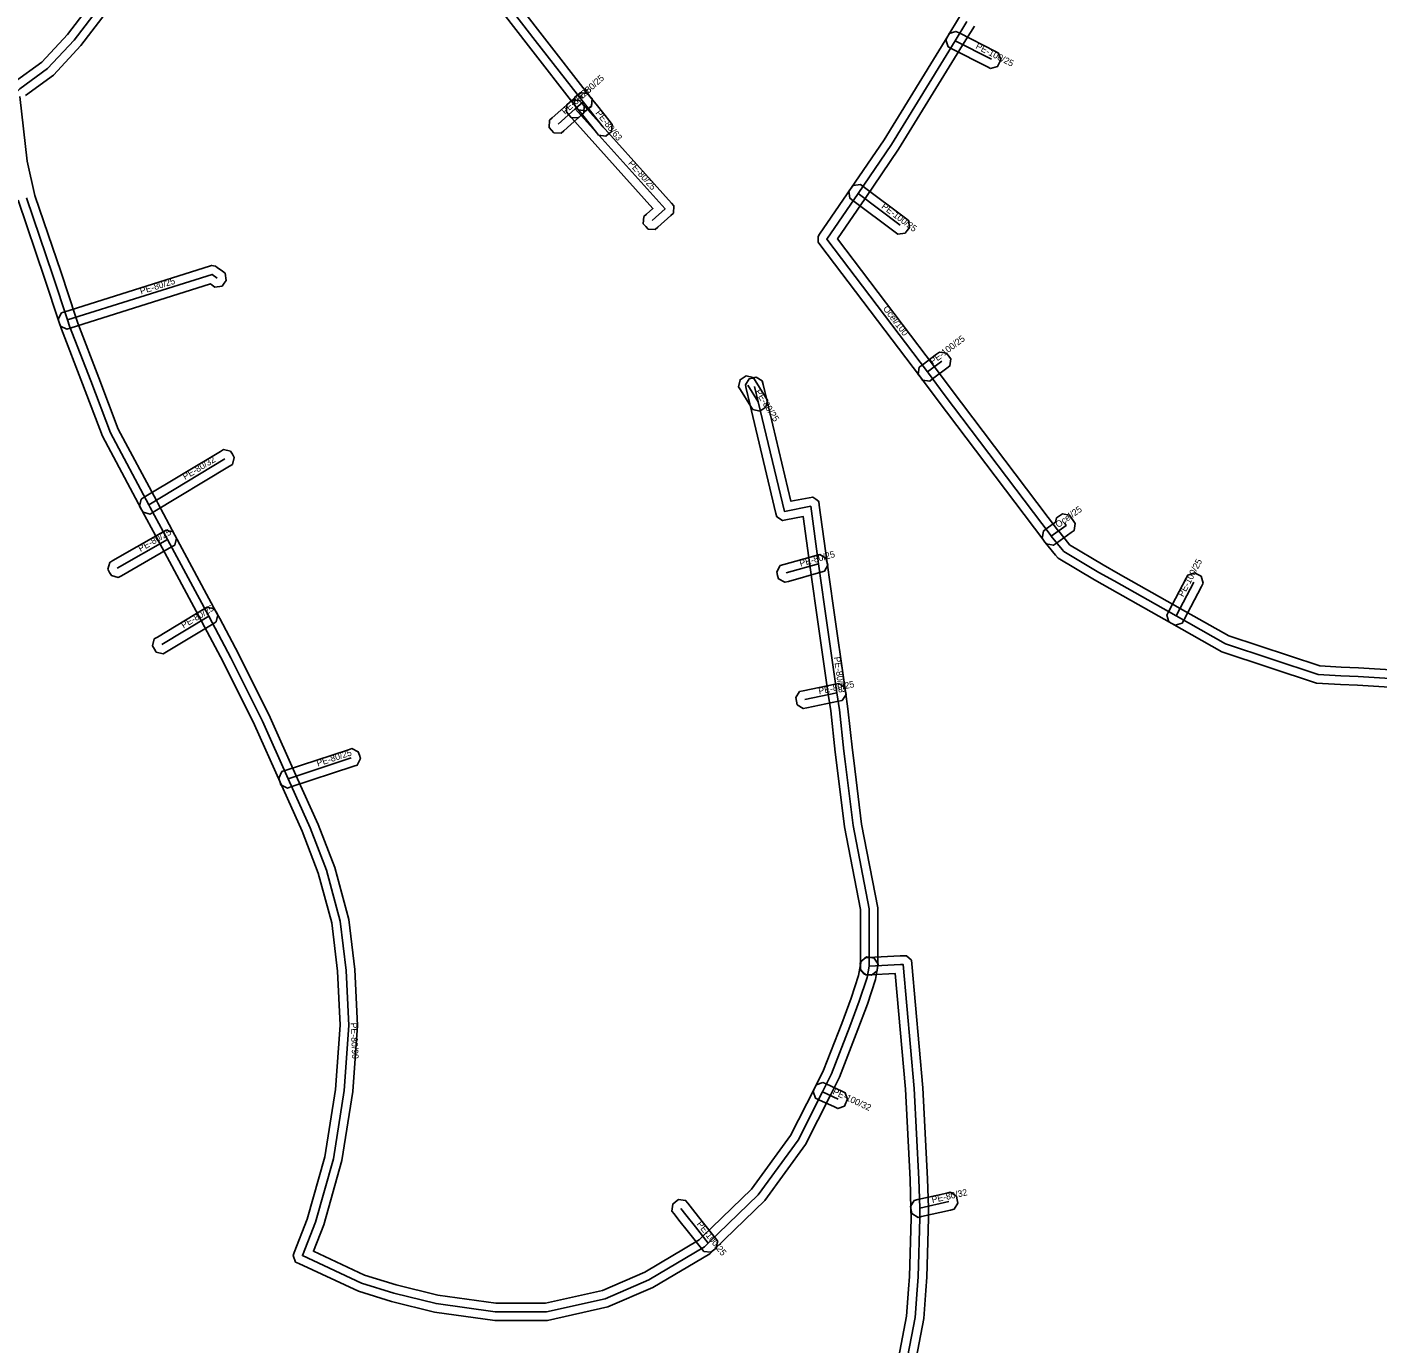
# Model space of a CAD drawing. Extents: x -569373 to -565022, y -1135090 to -1131496.
# Drawn here: x -565687.7 to -565532.3, y -1133998.2 to -1133846.6 of the extents above; entities that cross this region are included whole.
import ezdxf

# ---------------------------------------------------------------- set-up
doc = ezdxf.new("R2010")
doc.units = 0
for name, color, linetype in [('1', 7, 'Continuous'), ('24', 7, 'Continuous'), ('30', 7, 'Continuous')]:
    doc.layers.add(name, color=color, linetype=linetype)

msp = doc.modelspace()

# ---------------------------------------------------------------- linework, layer by layer
at = {"layer": '1'}
for points in [[(-565640.381, -1133832.1), (-565628.421, -1133847.596), (-565622.903, -1133854.633), (-565622.647, -1133854.959), (-565622.747, -1133855.781), (-565623.073, -1133856.037), (-565623.399, -1133856.293), (-565624.221, -1133856.193), (-565624.477, -1133855.867), (-565629.999, -1133848.824), (-565641.919, -1133833.38)], [(-565689.224, -1133853.006), (-565686.016, -1133850.687), (-565683.056, -1133847.495), (-565673.112, -1133834.485)], [(-565671.524, -1133835.699), (-565681.524, -1133848.785), (-565684.684, -1133852.193), (-565687.896, -1133854.514)], [(-565525.264, -1133923.028), (-565534.506, -1133922.438), (-565536.498, -1133922.344), (-565539.245, -1133922.212), (-565550.147, -1133918.589), (-565555.911, -1133915.341), (-565563.054, -1133911.303), (-565564.802, -1133910.315), (-565568.991, -1133907.816), (-565569.299, -1133907.46), (-565570.627, -1133905.802), (-565570.642, -1133905.771), (-565582.93, -1133889.551), (-565584.744, -1133887.114), (-565584.852, -1133886.967), (-565596.427, -1133871.673), (-565596.621, -1133871.416), (-565596.637, -1133870.772), (-565596.456, -1133870.506), (-565592.866, -1133865.246), (-565589.04, -1133859.636), (-565581.702, -1133847.696), (-565580.34, -1133845.483)], [(-565578.64, -1133846.537), (-565579.998, -1133848.744), (-565587.36, -1133860.724), (-565591.214, -1133866.374), (-565594.399, -1133871.04), (-565583.248, -1133885.773), (-565583.136, -1133885.926), (-565581.33, -1133888.349), (-565568.937, -1133904.71), (-565568.932, -1133904.719), (-565567.761, -1133906.18), (-565567.689, -1133906.264), (-565563.798, -1133908.585), (-565562.07, -1133909.563), (-565554.929, -1133913.599), (-565549.333, -1133916.751), (-565538.875, -1133920.228), (-565536.402, -1133920.346), (-565534.394, -1133920.442), (-565525.136, -1133921.032)], [(-565688.56, -1133854.659), (-565687.713, -1133862.093), (-565686.826, -1133866.029), (-565683.802, -1133874.933), (-565682.109, -1133880.069), (-565681.887, -1133880.755), (-565679.456, -1133887.032), (-565677.217, -1133892.946), (-565672.827, -1133901.19), (-565672.668, -1133901.488), (-565670.689, -1133905.177), (-565665.93, -1133914.035), (-565665.539, -1133914.756), (-565663.361, -1133918.832), (-565659.725, -1133926.154), (-565656.757, -1133932.802), (-565654.207, -1133938.495), (-565652.289, -1133943.448), (-565650.666, -1133949.438), (-565649.963, -1133955.196), (-565649.668, -1133961.634), (-565650.226, -1133969.244), (-565651.471, -1133977.184), (-565653.561, -1133984.589), (-565654.747, -1133987.62), (-565648.848, -1133990.366), (-565645.211, -1133991.506), (-565640.432, -1133992.677), (-565633.742, -1133993.61), (-565628.012, -1133993.59), (-565621.479, -1133992.134), (-565616.585, -1133990.027), (-565610.313, -1133986.305), (-565609.969, -1133985.985), (-565604.288, -1133980.482), (-565599.796, -1133974.297), (-565597.022, -1133968.819), (-565595.995, -1133966.784), (-565593.915, -1133961.386), (-565592.844, -1133958.499), (-565591.972, -1133955.856), (-565591.755, -1133954.617), (-565591.683, -1133954.209), (-565591.005, -1133953.733), (-565590.597, -1133953.805), (-565590.189, -1133953.877), (-565589.713, -1133954.555), (-565589.785, -1133954.963), (-565590.028, -1133956.344), (-565590.956, -1133959.161), (-565592.045, -1133962.094), (-565594.165, -1133967.596), (-565595.238, -1133969.721), (-565598.084, -1133975.343), (-565602.772, -1133981.798), (-565608.591, -1133987.435), (-565609.107, -1133987.915), (-565615.675, -1133991.813), (-565620.861, -1133994.046), (-565627.788, -1133995.59), (-565633.878, -1133995.61), (-565640.808, -1133994.643), (-565645.749, -1133993.434), (-565649.572, -1133992.234), (-565656.442, -1133989.037), (-565656.801, -1133988.87), (-565657.095, -1133988.134), (-565656.951, -1133987.766), (-565655.459, -1133983.951), (-565653.429, -1133976.756), (-565652.214, -1133969.016), (-565651.672, -1133961.606), (-565651.957, -1133955.364), (-565652.634, -1133949.822), (-565654.191, -1133944.072), (-565656.053, -1133939.265), (-565658.583, -1133933.618), (-565661.535, -1133927.006), (-565665.139, -1133919.748), (-565667.301, -1133915.704), (-565667.69, -1133914.985), (-565672.451, -1133906.123), (-565674.432, -1133902.432), (-565674.593, -1133902.13), (-565679.043, -1133893.774), (-565681.324, -1133887.748), (-565683.773, -1133881.425), (-565684.011, -1133880.691), (-565685.698, -1133875.567), (-565688.754, -1133866.571)], [(-565588.581, -1134006.194), (-565586.453, -1133995.11), (-565586.234, -1133992.009), (-565586.129, -1133990.528), (-565585.91, -1133983.827), (-565585.94, -1133982.688), (-565586.039, -1133979.371), (-565586.578, -1133968.96), (-565587.752, -1133955.65), (-565590.723, -1133955.789), (-565591.137, -1133955.808), (-565591.75, -1133955.251), (-565591.769, -1133954.837), (-565591.788, -1133954.423), (-565591.231, -1133953.81), (-565590.817, -1133953.791), (-565587.18, -1133953.621), (-565586.873, -1133953.611), (-565586.475, -1133953.598), (-565585.879, -1133954.125), (-565585.844, -1133954.522), (-565584.582, -1133968.82), (-565584.041, -1133979.289), (-565583.94, -1133982.632), (-565583.91, -1133983.833), (-565584.131, -1133990.632), (-565584.238, -1133992.151), (-565584.467, -1133995.37), (-565586.619, -1134006.586)]]:
    msp.add_lwpolyline(points, dxfattribs=at)
for points in [[(-565576.766, -1133851.429), (-565577.135, -1133851.241), (-565581.305, -1133849.111), (-565581.674, -1133848.923), (-565581.929, -1133848.134), (-565581.741, -1133847.765), (-565581.553, -1133847.396), (-565580.764, -1133847.141), (-565580.395, -1133847.329), (-565576.225, -1133849.459), (-565575.856, -1133849.647), (-565575.601, -1133850.436), (-565575.789, -1133850.805), (-565575.977, -1133851.174)], [(-565627.557, -1133857.383), (-565627.249, -1133857.106), (-565625.269, -1133855.326), (-565624.961, -1133855.049), (-565624.133, -1133855.093), (-565623.856, -1133855.401), (-565623.579, -1133855.709), (-565623.623, -1133856.537), (-565623.931, -1133856.814), (-565625.911, -1133858.594), (-565626.219, -1133858.871), (-565627.047, -1133858.827), (-565627.324, -1133858.519), (-565627.601, -1133858.211)], [(-565624.133, -1133855.094), (-565623.856, -1133855.402), (-565613.506, -1133866.932), (-565613.229, -1133867.24), (-565613.273, -1133868.067), (-565613.581, -1133868.344), (-565615.071, -1133869.684), (-565615.379, -1133869.961), (-565616.207, -1133869.917), (-565616.484, -1133869.609), (-565616.761, -1133869.301), (-565616.717, -1133868.473), (-565616.409, -1133868.196), (-565615.662, -1133867.525), (-565625.344, -1133856.738), (-565625.621, -1133856.43), (-565625.576, -1133855.603), (-565625.268, -1133855.326), (-565624.96, -1133855.049)], [(-565625.577, -1133855.605), (-565625.269, -1133855.327), (-565624.359, -1133854.507), (-565624.052, -1133854.23), (-565623.225, -1133854.273), (-565622.947, -1133854.581), (-565622.67, -1133854.888), (-565622.713, -1133855.715), (-565623.021, -1133855.993), (-565623.931, -1133856.813), (-565624.238, -1133857.09), (-565625.065, -1133857.047), (-565625.343, -1133856.739), (-565625.62, -1133856.432)], [(-565623.16, -1133854.306), (-565622.904, -1133854.632), (-565622.055, -1133855.71), (-565620.597, -1133857.548), (-565620.339, -1133857.873), (-565620.434, -1133858.696), (-565620.758, -1133858.953), (-565621.083, -1133859.211), (-565621.906, -1133859.116), (-565622.163, -1133858.792), (-565623.625, -1133856.95), (-565624.476, -1133855.868), (-565624.732, -1133855.543), (-565624.634, -1133854.72), (-565624.308, -1133854.464), (-565623.983, -1133854.208)], [(-565591.771, -1133864.761), (-565591.44, -1133865.01), (-565586.57, -1133868.66), (-565586.239, -1133868.909), (-565586.121, -1133869.729), (-565586.37, -1133870.06), (-565586.619, -1133870.391), (-565587.439, -1133870.509), (-565587.77, -1133870.26), (-565592.64, -1133866.61), (-565592.971, -1133866.361), (-565593.089, -1133865.541), (-565592.84, -1133865.21), (-565592.591, -1133864.879)], [(-565683.756, -1133879.551), (-565683.361, -1133879.426), (-565666.711, -1133874.176), (-565666.482, -1133874.104), (-565666.007, -1133874.184), (-565665.814, -1133874.327), (-565665.234, -1133874.757), (-565664.901, -1133875.003), (-565664.78, -1133875.823), (-565665.027, -1133876.156), (-565665.273, -1133876.489), (-565666.093, -1133876.61), (-565666.426, -1133876.363), (-565666.596, -1133876.237), (-565682.759, -1133881.334), (-565683.154, -1133881.458), (-565683.889, -1133881.076), (-565684.014, -1133880.681), (-565684.138, -1133880.286)], [(-565584.984, -1133885.823), (-565584.654, -1133885.573), (-565583.004, -1133884.323), (-565582.674, -1133884.073), (-565581.853, -1133884.186), (-565581.603, -1133884.516), (-565581.353, -1133884.846), (-565581.466, -1133885.667), (-565581.796, -1133885.917), (-565583.446, -1133887.167), (-565583.776, -1133887.417), (-565584.597, -1133887.304), (-565584.847, -1133886.974), (-565585.097, -1133886.644)], [(-565604.144, -1133890.694), (-565604.365, -1133890.344), (-565605.585, -1133888.414), (-565605.807, -1133888.064), (-565605.624, -1133887.256), (-565605.274, -1133887.035), (-565604.924, -1133886.813), (-565604.116, -1133886.996), (-565603.895, -1133887.346), (-565602.675, -1133889.276), (-565602.453, -1133889.626), (-565602.636, -1133890.434), (-565602.986, -1133890.655), (-565603.336, -1133890.877)], [(-565591.818, -1133955.059), (-565591.76, -1133954.649), (-565591.74, -1133954.509), (-565591.74, -1133948.277), (-565593.598, -1133938.748), (-565594.523, -1133931.336), (-565594.654, -1133930.14), (-565595.182, -1133925.396), (-565595.46, -1133923.462), (-565596.89, -1133913.53), (-565597.571, -1133908.606), (-565598.337, -1133903.02), (-565600.332, -1133903.402), (-565600.726, -1133903.478), (-565601.4, -1133903.042), (-565601.493, -1133902.651), (-565604.493, -1133890.041), (-565604.913, -1133888.271), (-565605.009, -1133887.868), (-565604.574, -1133887.163), (-565604.171, -1133887.067), (-565603.768, -1133886.971), (-565603.063, -1133887.406), (-565602.967, -1133887.809), (-565602.547, -1133889.579), (-565599.769, -1133901.258), (-565597.678, -1133900.858), (-565597.256, -1133900.777), (-565596.907, -1133901.028), (-565596.558, -1133901.278), (-565596.499, -1133901.704), (-565595.589, -1133908.334), (-565594.91, -1133913.25), (-565593.48, -1133923.178), (-565593.198, -1133925.144), (-565592.666, -1133929.92), (-565592.537, -1133931.104), (-565591.622, -1133938.432), (-565589.74, -1133948.083), (-565589.74, -1133954.651), (-565589.78, -1133954.931), (-565589.838, -1133955.341), (-565590.501, -1133955.838), (-565590.911, -1133955.78), (-565591.321, -1133955.722)], [(-565674.582, -1133901.018), (-565674.227, -1133900.804), (-565665.457, -1133895.514), (-565665.102, -1133895.3), (-565664.298, -1133895.498), (-565664.084, -1133895.853), (-565663.87, -1133896.208), (-565664.068, -1133897.012), (-565664.423, -1133897.226), (-565673.193, -1133902.516), (-565673.548, -1133902.73), (-565674.352, -1133902.532), (-565674.566, -1133902.177), (-565674.78, -1133901.822)], [(-565570.36, -1133904.445), (-565569.281, -1133903.677), (-565569.189, -1133903.172), (-565568.848, -1133902.937), (-565568.507, -1133902.702), (-565567.692, -1133902.851), (-565567.457, -1133903.192), (-565567.257, -1133903.482), (-565567.024, -1133903.819), (-565567.166, -1133904.627), (-565567.5, -1133904.865), (-565569.2, -1133906.075), (-565569.538, -1133906.315), (-565570.355, -1133906.178), (-565570.595, -1133905.84), (-565570.835, -1133905.502), (-565570.698, -1133904.685)], [(-565670.713, -1133906.312), (-565671.073, -1133906.518), (-565676.853, -1133909.828), (-565677.213, -1133910.034), (-565678.012, -1133909.817), (-565678.218, -1133909.457), (-565678.424, -1133909.097), (-565678.207, -1133908.298), (-565677.847, -1133908.092), (-565672.067, -1133904.782), (-565671.707, -1133904.576), (-565670.908, -1133904.793), (-565670.702, -1133905.153), (-565670.496, -1133905.513)], [(-565600.999, -1133908.669), (-565600.6, -1133908.557), (-565596.85, -1133907.507), (-565596.451, -1133907.395), (-565595.729, -1133907.801), (-565595.617, -1133908.2), (-565595.505, -1133908.599), (-565595.911, -1133909.321), (-565596.31, -1133909.433), (-565600.06, -1133910.483), (-565600.459, -1133910.595), (-565601.181, -1133910.189), (-565601.293, -1133909.79), (-565601.405, -1133909.391)], [(-565552.293, -1133910.691), (-565552.486, -1133911.057), (-565554.536, -1133914.937), (-565554.729, -1133915.303), (-565555.521, -1133915.547), (-565555.887, -1133915.354), (-565556.253, -1133915.161), (-565556.497, -1133914.369), (-565556.304, -1133914.003), (-565554.254, -1133910.123), (-565554.061, -1133909.757), (-565553.269, -1133909.513), (-565552.903, -1133909.706), (-565552.537, -1133909.899)], [(-565665.939, -1133915.152), (-565666.294, -1133915.366), (-565671.684, -1133918.616), (-565672.039, -1133918.83), (-565672.842, -1133918.631), (-565673.056, -1133918.276), (-565673.27, -1133917.921), (-565673.071, -1133917.118), (-565672.716, -1133916.904), (-565667.326, -1133913.654), (-565666.971, -1133913.44), (-565666.168, -1133913.639), (-565665.954, -1133913.994), (-565665.74, -1133914.349)], [(-565593.862, -1133924.215), (-565594.268, -1133924.299), (-565597.948, -1133925.059), (-565598.354, -1133925.143), (-565599.045, -1133924.688), (-565599.129, -1133924.282), (-565599.213, -1133923.876), (-565598.758, -1133923.185), (-565598.352, -1133923.101), (-565594.672, -1133922.341), (-565594.266, -1133922.257), (-565593.575, -1133922.712), (-565593.491, -1133923.118), (-565593.407, -1133923.524)], [(-565658.377, -1133932.39), (-565657.983, -1133932.26), (-565650.723, -1133929.87), (-565650.329, -1133929.74), (-565649.59, -1133930.113), (-565649.46, -1133930.507), (-565649.33, -1133930.901), (-565649.703, -1133931.64), (-565650.097, -1133931.77), (-565657.357, -1133934.16), (-565657.751, -1133934.29), (-565658.49, -1133933.917), (-565658.62, -1133933.523), (-565658.75, -1133933.129)], [(-565596.082, -1133968.189), (-565595.707, -1133968.364), (-565593.907, -1133969.204), (-565593.532, -1133969.379), (-565593.249, -1133970.158), (-565593.424, -1133970.533), (-565593.599, -1133970.908), (-565594.378, -1133971.191), (-565594.753, -1133971.016), (-565596.553, -1133970.176), (-565596.928, -1133970.001), (-565597.211, -1133969.222), (-565597.036, -1133968.847), (-565596.861, -1133968.472)], [(-565585.563, -1133981.775), (-565585.159, -1133981.684), (-565581.819, -1133980.934), (-565581.415, -1133980.843), (-565580.715, -1133981.287), (-565580.624, -1133981.691), (-565580.533, -1133982.095), (-565580.977, -1133982.795), (-565581.381, -1133982.886), (-565584.721, -1133983.636), (-565585.125, -1133983.727), (-565585.825, -1133983.283), (-565585.916, -1133982.879), (-565586.007, -1133982.475)], [(-565609.81, -1133987.654), (-565610.066, -1133987.329), (-565611.544, -1133985.45), (-565612.665, -1133984.04), (-565613.216, -1133983.338), (-565613.472, -1133983.012), (-565613.374, -1133982.19), (-565613.048, -1133981.934), (-565612.722, -1133981.678), (-565611.9, -1133981.776), (-565611.644, -1133982.102), (-565611.095, -1133982.8), (-565609.976, -1133984.21), (-565608.494, -1133986.091), (-565608.238, -1133986.417), (-565608.336, -1133987.24), (-565608.661, -1133987.496), (-565608.987, -1133987.752)]]:
    msp.add_lwpolyline(points, close=True, dxfattribs=at)
at = {"layer": '24'}
for points in [[(-565689.7, -1133854.98), (-565688.56, -1133853.76), (-565685.35, -1133851.44), (-565682.29, -1133848.14), (-565672.318, -1133835.092), (-565671.59, -1133834.14), (-565658.14, -1133816.52), (-565652.84, -1133820.6), (-565648.38, -1133824.67), (-565641.15, -1133832.74), (-565629.21, -1133848.21), (-565623.69, -1133855.25)], [(-565579.49, -1133846.01), (-565580.85, -1133848.22), (-565588.2, -1133860.18), (-565592.04, -1133865.81), (-565595.63, -1133871.07), (-565584.05, -1133886.37), (-565583.94, -1133886.52), (-565582.13, -1133888.95), (-565569.79, -1133905.24), (-565569.78, -1133905.26), (-565568.53, -1133906.82), (-565568.34, -1133907.04), (-565564.3, -1133909.45), (-565562.562, -1133910.433), (-565555.42, -1133914.47), (-565549.74, -1133917.67), (-565539.06, -1133921.22), (-565536.45, -1133921.345), (-565534.45, -1133921.44), (-565525.2, -1133922.03), (-565516.66, -1133922.58), (-565513.93, -1133922.75), (-565511.94, -1133922.9), (-565507.76, -1133923.22)], [(-565576.68, -1133850.35), (-565580.85, -1133848.22)], [(-565624.6, -1133856.07), (-565623.69, -1133855.25)], [(-565623.69, -1133855.25), (-565622.84, -1133856.33), (-565621.38, -1133858.17)], [(-565626.58, -1133857.85), (-565624.6, -1133856.07)], [(-565624.6, -1133856.07), (-565614.25, -1133867.6), (-565615.74, -1133868.94)], [(-565687.79, -1133866.3), (-565684.75, -1133875.25), (-565683.06, -1133880.38), (-565682.83, -1133881.09), (-565680.39, -1133887.39), (-565678.13, -1133893.36), (-565673.71, -1133901.66), (-565673.55, -1133901.96), (-565671.57, -1133905.65), (-565666.81, -1133914.51), (-565666.42, -1133915.23), (-565664.25, -1133919.29), (-565660.63, -1133926.58), (-565657.67, -1133933.21), (-565655.13, -1133938.88), (-565653.24, -1133943.76), (-565651.65, -1133949.63), (-565650.96, -1133955.28), (-565650.67, -1133961.62), (-565651.22, -1133969.13), (-565652.45, -1133976.97), (-565654.51, -1133984.27), (-565656.02, -1133988.13), (-565649.21, -1133991.3), (-565645.48, -1133992.47), (-565640.62, -1133993.66), (-565633.81, -1133994.61), (-565627.9, -1133994.59), (-565621.17, -1133993.09), (-565616.13, -1133990.92), (-565609.71, -1133987.11), (-565609.28, -1133986.71), (-565603.53, -1133981.14), (-565598.94, -1133974.82), (-565596.13, -1133969.27), (-565595.08, -1133967.19), (-565592.98, -1133961.74), (-565591.9, -1133958.83), (-565591, -1133956.1), (-565590.77, -1133954.79)], [(-565592.04, -1133865.81), (-565587.17, -1133869.46)], [(-565683.06, -1133880.38), (-565666.41, -1133875.13), (-565665.83, -1133875.56)], [(-565584.05, -1133886.37), (-565582.4, -1133885.12)], [(-565603.52, -1133889.81), (-565604.74, -1133887.88)], [(-565590.77, -1133954.79), (-565590.74, -1133954.58), (-565590.74, -1133948.18), (-565592.61, -1133938.59), (-565593.53, -1133931.22), (-565593.66, -1133930.03), (-565594.19, -1133925.27), (-565594.47, -1133923.32), (-565595.9, -1133913.39), (-565596.58, -1133908.47), (-565597.49, -1133901.84), (-565600.52, -1133902.42), (-565603.52, -1133889.81), (-565603.94, -1133888.04)], [(-565673.71, -1133901.66), (-565664.94, -1133896.37)], [(-565569.78, -1133905.26), (-565568.08, -1133904.05), (-565568.28, -1133903.76)], [(-565671.57, -1133905.65), (-565677.35, -1133908.96)], [(-565600.33, -1133909.52), (-565596.58, -1133908.47)], [(-565553.37, -1133910.59), (-565555.42, -1133914.47)], [(-565666.81, -1133914.51), (-565672.2, -1133917.76)], [(-565594.47, -1133923.32), (-565598.15, -1133924.08)], [(-565657.67, -1133933.21), (-565650.41, -1133930.82)], [(-565590.77, -1133954.79), (-565587.14, -1133954.62), (-565586.84, -1133954.61), (-565585.58, -1133968.89), (-565585.04, -1133979.33), (-565584.94, -1133982.66), (-565584.91, -1133983.83), (-565585.13, -1133990.58), (-565585.236, -1133992.08), (-565585.46, -1133995.24), (-565587.6, -1134006.39)], [(-565596.13, -1133969.27), (-565594.33, -1133970.11)], [(-565609.28, -1133986.71), (-565610.76, -1133984.83), (-565611.88, -1133983.42), (-565612.43, -1133982.72)], [(-565584.94, -1133982.66), (-565581.6, -1133981.91)]]:
    msp.add_lwpolyline(points, dxfattribs=at)

# ---------------------------------------------------------------- texts
at = {"layer": '30'}
for s, rotation, p in [('PE-100/25', 332.94245, (-565578.565, -1133849.085)), ('PE-80/25', 42.02198, (-565624.308, -1133855.427)), ('PE-80/25', 41.95522, (-565625.79, -1133856.76)), ('PE-80/63', 308.43124, (-565622.306, -1133856.551)), ('PE-80/25', 311.913, (-565618.556, -1133862.381)), ('PE-100/25', 323.14893, (-565589.405, -1133867.435)), ('PE-80/25', 17.50086, (-565674.591, -1133877.446)), ('Ocel/100', 307.12072, (-565589.206, -1133879.093)), ('PE-100/25', 37.14669, (-565583.425, -1133885.545)), ('PE-80/25', 302.29798, (-565603.93, -1133888.645)), ('PE-80/32', 31.09807, (-565669.525, -1133898.815)), ('Ocel/25', 35.44192, (-565568.986, -1133904.353)), ('PE-80/25', 29.79823, (-565674.66, -1133907.105)), ('PE-80/25', 15.64225, (-565598.655, -1133908.795)), ('PE-100/25', 62.15024, (-565554.595, -1133912.33)), ('PE-80/25', 31.08865, (-565669.705, -1133915.935)), ('PE-80/63', 278.19472, (-565594.832, -1133919.215)), ('PE-80/25', 11.66877, (-565596.51, -1133923.5)), ('PE-80/25', 18.2216, (-565654.24, -1133931.815)), ('PE-80/90', 272.61896, (-565650.475, -1133961.315)), ('PE-100/32', 334.98311, (-565595.03, -1133969.49)), ('PE-80/32', 12.65589, (-565583.47, -1133982.085)), ('PE-100/25', 308.46104, (-565610.653, -1133984.513))]:
    msp.add_text(s, height=0.75, rotation=rotation, dxfattribs=at).set_placement(p)

doc.saveas('drawing.dxf')
